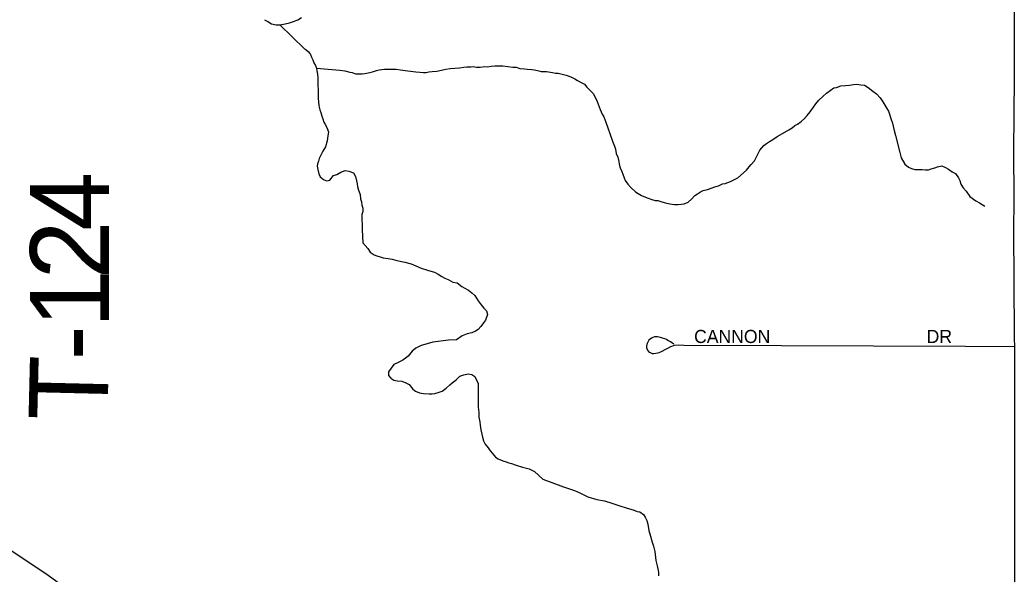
# Model space of a CAD drawing. Extents: x -17 to 88, y -5 to 22.
# Drawn here: x -14.955 to -14.238, y 18.289 to 18.689 of the extents above; entities that cross this region are included whole.
import ezdxf

# ---------------------------------------------------------------- set-up
doc = ezdxf.new("R2010")
doc.units = 0
for name, color, linetype in [('GM_X_Major_River', 7, 'Continuous'), ('GM_X_Minor_River', 7, 'Continuous'), ('GM_X_Township_Road', 7, 'Continuous'), ('GM_X_Township_Road_Text', 7, 'Continuous'), ('GM_X_Township_Subdivision', 7, 'Continuous'), ('GM_X_Township_Subdivision_Text', 7, 'Continuous'), ('GM_X_US_Route', 7, 'Continuous')]:
    doc.layers.add(name, color=color, linetype=linetype)

msp = doc.modelspace()

# ---------------------------------------------------------------- linework, layer by layer
at = {"layer": 'GM_X_Major_River'}
msp.add_lwpolyline([(-14.77856, 18.68878), (-14.7763, 18.6876), (-14.77367, 18.68603), (-14.77027, 18.68521), (-14.76761, 18.68516), (-14.76379, 18.68585), (-14.76074, 18.68655), (-14.75768, 18.68763), (-14.75461, 18.68871), (-14.75192, 18.69056)], dxfattribs=at)
at = {"layer": 'GM_X_Minor_River'}
for points in [[(-14.76761, 18.68516), (-14.74984, 18.66793)], [(-14.74984, 18.66793), (-14.74893, 18.66734), (-14.74706, 18.66579), (-14.74557, 18.66386), (-14.74485, 18.66195), (-14.74374, 18.66003), (-14.74303, 18.65774), (-14.74192, 18.65582), (-14.7412, 18.65391), (-14.74085, 18.652), (-14.74051, 18.64972), (-14.74018, 18.64705), (-14.74022, 18.64478), (-14.74028, 18.64174), (-14.73997, 18.63832), (-14.74008, 18.63186), (-14.73974, 18.62996), (-14.73942, 18.62691), (-14.73872, 18.62386), (-14.73799, 18.62195), (-14.73728, 18.61928), (-14.73655, 18.61737), (-14.73584, 18.61507), (-14.73473, 18.61316), (-14.73327, 18.61009), (-14.73255, 18.6078), (-14.73298, 18.60515), (-14.73342, 18.60174), (-14.73465, 18.59721), (-14.73661, 18.5942), (-14.73818, 18.5912), (-14.73937, 18.58894), (-14.73978, 18.58705), (-14.74058, 18.58516), (-14.74061, 18.58326), (-14.74027, 18.58098), (-14.73957, 18.57793), (-14.73847, 18.57563), (-14.73623, 18.57369), (-14.73396, 18.57289), (-14.73168, 18.57323), (-14.72895, 18.57659), (-14.72666, 18.57731), (-14.72358, 18.57915), (-14.72052, 18.58023), (-14.71787, 18.5798), (-14.71447, 18.5786), (-14.713, 18.57592), (-14.71229, 18.57287), (-14.71196, 18.57058), (-14.71161, 18.56867), (-14.7109, 18.566), (-14.70982, 18.56295), (-14.70949, 18.5599), (-14.70878, 18.55761), (-14.70844, 18.55533), (-14.70772, 18.55303), (-14.70776, 18.55076), (-14.70857, 18.54849), (-14.70841, 18.53761)], [(-14.7412, 18.65391), (-14.7245, 18.65246), (-14.7207, 18.65201), (-14.7173, 18.65119), (-14.7154, 18.65077), (-14.71314, 18.64997), (-14.71124, 18.64993), (-14.70819, 18.64988), (-14.70629, 18.65022), (-14.70285, 18.65092), (-14.70094, 18.65126), (-14.69788, 18.65234), (-14.69598, 18.65269), (-14.69407, 18.65303), (-14.69216, 18.65337), (-14.68988, 18.65333), (-14.68646, 18.65327), (-14.6838, 18.65322), (-14.68077, 18.65278), (-14.67736, 18.65234), (-14.67356, 18.65189), (-14.66977, 18.65144), (-14.66673, 18.651), (-14.66408, 18.65095), (-14.66218, 18.65092), (-14.66027, 18.65126), (-14.65798, 18.6516), (-14.65455, 18.65192), (-14.65112, 18.65261), (-14.64806, 18.65331), (-14.64502, 18.65364), (-14.64159, 18.65395), (-14.63816, 18.65427), (-14.63511, 18.65459), (-14.63283, 18.65493), (-14.63016, 18.65488), (-14.62826, 18.65522), (-14.62599, 18.6548), (-14.62332, 18.65475), (-14.62028, 18.65508), (-14.618, 18.65503), (-14.61533, 18.65536), (-14.61266, 18.65569), (-14.60962, 18.65564), (-14.60696, 18.65559), (-14.59975, 18.65469), (-14.59747, 18.65465), (-14.59483, 18.65384), (-14.59141, 18.6534), (-14.58951, 18.65336), (-14.5861, 18.65292), (-14.5842, 18.65289), (-14.58118, 18.65207), (-14.57928, 18.65166), (-14.57738, 18.65162), (-14.57548, 18.65158), (-14.57131, 18.65075), (-14.56904, 18.65032), (-14.56714, 18.65029), (-14.56336, 18.64946), (-14.56146, 18.64904), (-14.55806, 18.64784), (-14.55505, 18.64627), (-14.55317, 18.64509), (-14.55016, 18.64352), (-14.54828, 18.64234), (-14.54641, 18.64041), (-14.54455, 18.63848), (-14.54194, 18.63577), (-14.54047, 18.63309), (-14.53901, 18.63002), (-14.53828, 18.62811), (-14.53756, 18.6262), (-14.53683, 18.62428), (-14.53537, 18.62084), (-14.53427, 18.61892), (-14.53354, 18.61701), (-14.53282, 18.6151), (-14.53138, 18.61089), (-14.52813, 18.60134), (-14.52668, 18.59789), (-14.52596, 18.5956), (-14.52526, 18.59255), (-14.52417, 18.58987), (-14.52346, 18.58682), (-14.52312, 18.58492), (-14.52241, 18.58225), (-14.52132, 18.57957), (-14.52059, 18.57765), (-14.5195, 18.57497), (-14.51878, 18.57306), (-14.51693, 18.57037), (-14.51469, 18.56805), (-14.51133, 18.56495), (-14.50945, 18.56378), (-14.50719, 18.56221), (-14.50418, 18.56102), (-14.50229, 18.56022), (-14.49964, 18.55942), (-14.49738, 18.55861), (-14.49548, 18.55858)], [(-14.49548, 18.55858), (-14.49245, 18.55776), (-14.4898, 18.55696), (-14.48678, 18.55614), (-14.48336, 18.55569), (-14.48071, 18.55565), (-14.47651, 18.55633), (-14.47345, 18.55741), (-14.47112, 18.55964), (-14.46879, 18.56226), (-14.46687, 18.56336), (-14.46457, 18.56484), (-14.46264, 18.56594), (-14.45959, 18.56664), (-14.45615, 18.56772), (-14.45423, 18.56844), (-14.45156, 18.56915), (-14.44887, 18.57062), (-14.44696, 18.57097), (-14.44505, 18.57169), (-14.44313, 18.57241), (-14.44007, 18.57388), (-14.43776, 18.57497), (-14.43158, 18.58055), (-14.42963, 18.5828), (-14.42808, 18.58467), (-14.42575, 18.58728), (-14.42416, 18.59067), (-14.42299, 18.59255), (-14.42181, 18.5948), (-14.41908, 18.59817), (-14.41715, 18.59965), (-14.41485, 18.60113), (-14.41254, 18.6026), (-14.40945, 18.60483), (-14.40715, 18.60592), (-14.401, 18.6096), (-14.39869, 18.61108), (-14.39676, 18.61257), (-14.39484, 18.61367), (-14.39215, 18.61552), (-14.38982, 18.61775), (-14.38788, 18.61999), (-14.38555, 18.62261), (-14.38321, 18.62598), (-14.38164, 18.62823), (-14.37931, 18.63085), (-14.3766, 18.63345), (-14.3739, 18.63606), (-14.3712, 18.63791), (-14.3685, 18.63976), (-14.36659, 18.6401), (-14.36353, 18.64118), (-14.36011, 18.6415), (-14.35744, 18.64183), (-14.35439, 18.64215), (-14.3521, 18.64249), (-14.34907, 18.64206), (-14.34642, 18.64163), (-14.34378, 18.64006), (-14.34041, 18.63734), (-14.33779, 18.63539), (-14.33518, 18.63268), (-14.33333, 18.62961), (-14.33186, 18.62731), (-14.33038, 18.625), (-14.32927, 18.62308), (-14.32856, 18.62079), (-14.32747, 18.61773), (-14.3264, 18.61429), (-14.32533, 18.6101), (-14.32428, 18.60552), (-14.32108, 18.59331), (-14.32002, 18.58949), (-14.31744, 18.58489), (-14.31482, 18.58256), (-14.31256, 18.58176), (-14.31029, 18.58096), (-14.30763, 18.5809), (-14.30497, 18.58086), (-14.30269, 18.58081), (-14.30041, 18.58077), (-14.2985, 18.5815), (-14.29582, 18.58221), (-14.2939, 18.58293), (-14.29085, 18.58363), (-14.28821, 18.58244), (-14.28595, 18.58126), (-14.28333, 18.57932), (-14.28107, 18.57813), (-14.27884, 18.57506), (-14.27774, 18.57314), (-14.27703, 18.57046), (-14.27556, 18.56778), (-14.27332, 18.56546), (-14.27073, 18.56161), (-14.26623, 18.55849), (-14.26359, 18.55692), (-14.26172, 18.55575), (-14.25984, 18.55457)], [(-14.70841, 18.53761), (-14.70791, 18.52821), (-14.70411, 18.52403), (-14.70259, 18.52138), (-14.69956, 18.51948), (-14.69766, 18.51872), (-14.69538, 18.51796), (-14.69311, 18.5172), (-14.68969, 18.51682), (-14.68666, 18.51644), (-14.68324, 18.5153), (-14.67755, 18.51416), (-14.67299, 18.51303), (-14.66958, 18.51151), (-14.66578, 18.50999), (-14.66123, 18.50847), (-14.65895, 18.50771), (-14.6563, 18.50695), (-14.65364, 18.50543), (-14.65098, 18.50391), (-14.64871, 18.50278), (-14.64643, 18.50164), (-14.64302, 18.49974), (-14.63998, 18.49936), (-14.63656, 18.4967), (-14.63429, 18.49556), (-14.63163, 18.49404), (-14.62935, 18.49214), (-14.62708, 18.49025), (-14.6248, 18.48645), (-14.62252, 18.48341), (-14.62062, 18.48113), (-14.61873, 18.47924), (-14.61797, 18.47658), (-14.61948, 18.4724), (-14.621, 18.4705), (-14.6229, 18.46784), (-14.62479, 18.46557), (-14.62669, 18.46442), (-14.62935, 18.46329), (-14.63276, 18.46253), (-14.63618, 18.461), (-14.64035, 18.45835), (-14.64604, 18.45796), (-14.65742, 18.45645), (-14.6616, 18.45531), (-14.66577, 18.45417), (-14.66956, 18.45227), (-14.67222, 18.44999), (-14.67525, 18.44657), (-14.67905, 18.44353), (-14.68284, 18.44163), (-14.6855, 18.44049), (-14.68739, 18.43784), (-14.68929, 18.43518), (-14.68929, 18.43252), (-14.68777, 18.43062), (-14.68549, 18.4291), (-14.68322, 18.42872), (-14.6798, 18.42834), (-14.67676, 18.4272), (-14.67449, 18.42607), (-14.67183, 18.42265), (-14.66993, 18.42113), (-14.6669, 18.41999), (-14.66424, 18.41961), (-14.66007, 18.41923), (-14.65779, 18.41923), (-14.65589, 18.41961), (-14.65362, 18.42037), (-14.65058, 18.42113), (-14.64793, 18.42341), (-14.64527, 18.42569), (-14.64338, 18.42721), (-14.64072, 18.42949), (-14.63806, 18.43215), (-14.63503, 18.4329), (-14.632, 18.43367), (-14.62934, 18.43328), (-14.62706, 18.43177), (-14.62478, 18.42683), (-14.62478, 18.42265), (-14.62478, 18.4181), (-14.62478, 18.41392), (-14.62478, 18.40975), (-14.6244, 18.40595), (-14.6244, 18.40253), (-14.62364, 18.39911), (-14.62326, 18.39683), (-14.62288, 18.39341), (-14.62212, 18.39038), (-14.62174, 18.3881), (-14.62098, 18.38544), (-14.61984, 18.38316), (-14.61756, 18.3805), (-14.61604, 18.37823), (-14.61452, 18.37633), (-14.61225, 18.37367), (-14.61035, 18.37253), (-14.60694, 18.37101), (-14.60466, 18.37025)], [(-14.60466, 18.37025), (-14.60276, 18.3695), (-14.60086, 18.36911), (-14.59745, 18.36798), (-14.5929, 18.36646), (-14.58796, 18.36532), (-14.58417, 18.36342), (-14.57809, 18.35773), (-14.56329, 18.35241), (-14.55533, 18.34976), (-14.55115, 18.34786), (-14.54584, 18.3452), (-14.53939, 18.3433), (-14.5337, 18.34216), (-14.52838, 18.34064), (-14.52345, 18.33875), (-14.51738, 18.33685), (-14.5132, 18.33571), (-14.51017, 18.33457), (-14.50827, 18.33419), (-14.50561, 18.33229), (-14.50447, 18.3304), (-14.50334, 18.32812), (-14.50258, 18.32546), (-14.50182, 18.3209), (-14.50068, 18.31672), (-14.49954, 18.31255), (-14.4984, 18.30951), (-14.49764, 18.30571), (-14.49688, 18.29926), (-14.49574, 18.29546), (-14.49498, 18.2909), (-14.49498, 18.28825)]]:
    msp.add_lwpolyline(points, dxfattribs=at)
at = {"layer": 'GM_X_Township_Road'}
for points in [[(-14.23835, 18.45341), (-14.23847, 18.45918), (-14.23864, 18.50207), (-14.23891, 18.53498), (-14.23877, 18.56106), (-14.23887, 18.59335), (-14.23875, 18.62131), (-14.23853, 18.64617), (-14.2384, 18.67724), (-14.23805, 18.77075)], [(-14.24188, 17.74432), (-14.24138, 17.87773), (-14.24096, 17.94173), (-14.24013, 18.05669), (-14.23974, 18.11387), (-14.23874, 18.20769), (-14.23817, 18.30588), (-14.23813, 18.38355), (-14.23821, 18.41649), (-14.23835, 18.45341)]]:
    msp.add_lwpolyline(points, dxfattribs=at)
at = {"layer": 'GM_X_Township_Subdivision'}
msp.add_lwpolyline([(-14.48384, 18.45505), (-14.48635, 18.45679), (-14.48817, 18.45784), (-14.48922, 18.45837), (-14.49044, 18.45898), (-14.49193, 18.45954), (-14.49344, 18.45998), (-14.49456, 18.46019), (-14.49566, 18.46039), (-14.49667, 18.46039), (-14.49773, 18.46028), (-14.49893, 18.45998), (-14.50004, 18.45942), (-14.50098, 18.45863), (-14.50175, 18.4579), (-14.50256, 18.45664), (-14.50311, 18.45553), (-14.50332, 18.45481), (-14.50355, 18.45372), (-14.5035, 18.45274), (-14.50333, 18.45189), (-14.50284, 18.45086), (-14.50204, 18.44986), (-14.50136, 18.44926), (-14.5005, 18.44883), (-14.4995, 18.44849), (-14.49835, 18.44831), (-14.49671, 18.44856), (-14.49537, 18.4488), (-14.49442, 18.44911), (-14.49221, 18.45001), (-14.49009, 18.45123), (-14.48827, 18.45226), (-14.48602, 18.45341), (-14.48335, 18.45438), (-14.48032, 18.45457), (-14.47662, 18.45448), (-14.46896, 18.45419), (-14.43789, 18.45431), (-14.40621, 18.45412), (-14.27383, 18.45368), (-14.23835, 18.45341)], dxfattribs=at)
at = {"layer": 'GM_X_US_Route'}
msp.add_lwpolyline([(-14.32001, 17.72212), (-14.33142, 17.7328), (-14.38039, 17.77872), (-14.43655, 17.83149), (-14.49828, 17.88925), (-14.53635, 17.92496), (-14.62263, 18.0056), (-14.65699, 18.03802), (-14.69282, 18.07159), (-14.72776, 18.1043), (-14.79651, 18.16909), (-14.83872, 18.20858), (-14.8648, 18.23254), (-14.87967, 18.24571), (-14.89154, 18.25571), (-14.90413, 18.26579), (-14.91943, 18.27745), (-14.93452, 18.28837), (-14.94832, 18.29788), (-14.96548, 18.30908)], dxfattribs=at)

# ---------------------------------------------------------------- texts
at = {"layer": 'GM_X_Township_Road_Text'}
for s, rotation, p in [('4', 89.99789, (-14.89064, 18.53686)), ('2', 89.98794, (-14.89064, 18.50185)), ('1', 89.92572, (-14.89069, 18.46679)), ('-', 89.7646, (-14.89079, 18.44328)), ('T', 88.63703, (-14.89182, 18.39957))]:
    msp.add_text(s, height=0.05682, rotation=rotation, dxfattribs=at).set_placement(p)
at = {"layer": 'GM_X_Township_Subdivision_Text'}
for s, p in [('CANNON', (-14.46925, 18.45594)), ('DR', (-14.30175, 18.45594))]:
    msp.add_text(s, height=0.00947, rotation=0.00001, dxfattribs=at).set_placement(p)

doc.saveas('drawing.dxf')
